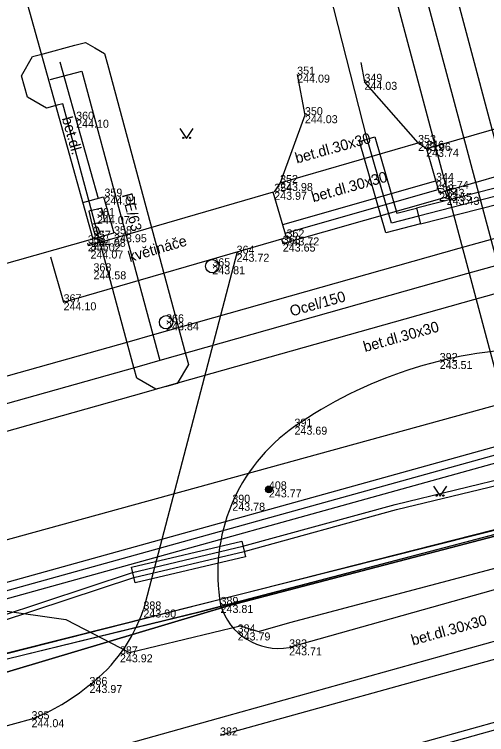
# Model space of a CAD drawing. Extents: x -599432 to -598680, y -1159407 to -1158632.
# Drawn here: x -599144.96 to -599127.27, y -1158925.7 to -1158898.71 of the extents above; entities that cross this region are included whole.
import ezdxf

# ---------------------------------------------------------------- set-up
doc = ezdxf.new("R2010")
doc.units = 0
for name, color, linetype in [('0004 VY - Body podrobné', 7, 'Continuous'), ('0005 VY - Body podrobné - čísla', 7, 'Continuous'), ('0006 VY - Body podrobné - výšky', 7, 'Continuous'), ('0007 ZA - Budova - zděná', 7, 'Continuous'), ('0014 ZA - Schody v terénu', 7, 'Continuous'), ('0025 ZA - Opěrná zeď', 7, 'Continuous'), ('0026 ZA - Polohopis - buňky', 7, 'Continuous'), ('0027 ZA - Silnice_cesta zpevněná', 7, 'Continuous'), ('0028 ZA - Silnice - nájezd na chodník', 7, 'Continuous'), ('0030 ZA - Chodník', 7, 'Continuous'), ('0031 ZA - Ostatní rozhraní', 7, 'Continuous'), ('0032 TE - Popis povrchu', 7, 'Continuous'), ('0034 ZA - Kultury - značky', 7, 'Continuous'), ('0074 TE - Vysvětlivky', 7, 'Continuous'), ('0075 ZA - BVK - kanalizace - buňky', 7, 'Continuous'), ('0116 PV - budova převzatá z mapy', 7, 'Continuous'), ('0202 PV - MUNI', 7, 'Continuous'), ('0206 PV - BVK - kanalizace - jednotná', 7, 'Continuous'), ('0211 PV - BVK - kanalizace - jednotná okraj', 7, 'Continuous'), ('0254 PV - TB - horkovod - vedení', 7, 'Continuous'), ('0255 PV - TB - horkovod - okraj', 7, 'Continuous'), ('0264 PV - TB - parovod mimo provoz', 7, 'Continuous'), ('0301 PV - RWE - popis', 7, 'Continuous'), ('0302 PV - RWE - NTL', 7, 'Continuous'), ('0303 PV - RWE - NTL přípojka', 7, 'Continuous'), ('0308 PV - RWE - ochranné pásmo', 7, 'Continuous'), ('0354 PV - EON - VN', 7, 'Continuous'), ('0359 PV - EON - sdělovací kabely', 7, 'Continuous'), ('0367 PV - EON - VN chránička', 7, 'Continuous'), ('0407 PV - TSB - kabelové vedení přibližný zákres', 7, 'Continuous'), ('0454 PV - O2 - kabel zaměřený', 7, 'Continuous'), ('0530 PV - T-mobile - optické kabely', 7, 'Continuous'), ('0552 PV - NETBOX - vedení', 7, 'Continuous'), ('0553 PV - NETBOX - chranička', 7, 'Continuous'), ('0652 PV - BKOM - kabely bez rozlišení', 7, 'Continuous'), ('0703 PV - DIAL TELECOM optický kabel', 7, 'Continuous'), ('0704 PV - ČD - kabely', 7, 'Continuous'), ('0750 ZA - nerozlišené sítě - buňky', 7, 'Continuous')]:
    doc.layers.add(name, color=color, linetype=linetype)

msp = doc.modelspace()

# ---------------------------------------------------------------- linework, layer by layer
at = {"layer": '0004 VY - Body podrobné'}
for p, q in [((-599134.37, -1158900.97), (-599134.37, -1158900.97)), ((-599131.85, -1158901.24), (-599131.85, -1158901.24)), ((-599134.08, -1158902.49), (-599134.08, -1158902.49)), ((-599142.65, -1158902.66), (-599142.65, -1158902.66)), ((-599129.84, -1158903.53), (-599129.84, -1158903.53)), ((-599129.54, -1158903.75), (-599129.54, -1158903.75)), ((-599129.17, -1158904.95), (-599129.17, -1158904.95)), ((-599135.01, -1158905.03), (-599135.01, -1158905.03)), ((-599135.23, -1158905.36), (-599135.23, -1158905.36)), ((-599129.05, -1158905.4), (-599129.05, -1158905.4)), ((-599141.59, -1158905.54), (-599141.59, -1158905.54)), ((-599128.77, -1158905.55), (-599128.77, -1158905.55)), ((-599141.87, -1158906.27), (-599141.87, -1158906.27)), ((-599142.02, -1158907.12), (-599142.02, -1158907.12)), ((-599141.23, -1158906.95), (-599141.23, -1158906.95)), ((-599134.77, -1158907.07), (-599134.77, -1158907.07)), ((-599142.21, -1158907.29), (-599142.21, -1158907.29)), ((-599134.91, -1158907.3), (-599134.91, -1158907.3)), ((-599142.11, -1158907.56), (-599142.11, -1158907.56)), ((-599136.64, -1158907.68), (-599136.64, -1158907.68)), ((-599137.55, -1158908.15), (-599137.55, -1158908.15)), ((-599142, -1158908.34), (-599142, -1158908.34)), ((-599143.12, -1158909.5), (-599143.12, -1158909.5)), ((-599139.28, -1158910.25), (-599139.28, -1158910.25)), ((-599129.03, -1158911.7), (-599129.03, -1158911.7)), ((-599134.47, -1158914.16), (-599134.47, -1158914.16)), ((-599135.43, -1158916.51), (-599135.43, -1158916.51)), ((-599136.8, -1158917.01), (-599136.8, -1158917.01)), ((-599137.24, -1158920.84), (-599137.24, -1158920.84)), ((-599140.13, -1158921.01), (-599140.13, -1158921.01)), ((-599136.6, -1158921.87), (-599136.6, -1158921.87)), ((-599134.67, -1158922.43), (-599134.67, -1158922.43)), ((-599141.01, -1158922.69), (-599141.01, -1158922.69)), ((-599142.15, -1158923.84), (-599142.15, -1158923.84)), ((-599144.32, -1158925.12), (-599144.32, -1158925.12))]:
    msp.add_line(p, q, dxfattribs=at)
at = {"layer": '0007 ZA - Budova - zděná'}
msp.add_line((-599202.3, -1158924.18), (-599142.02, -1158907.12), dxfattribs=at)
at = {"layer": '0014 ZA - Schody v terénu'}
for p, q in [((-599135.01, -1158905.03), (-599129.84, -1158903.53)), ((-599134.911, -1158906.586), (-599129.179, -1158904.953)), ((-599134.818, -1158906.906), (-599129.087, -1158905.272)), ((-599128.831, -1158905.337), (-599128.77, -1158905.55)), ((-599134.91, -1158907.3), (-599128.77, -1158905.55)), ((-599134.961, -1158907.126), (-599134.91, -1158907.3))]:
    msp.add_line(p, q, dxfattribs=at)
at = {"layer": '0025 ZA - Opěrná zeď'}
for p, q in [((-599122.539, -1158901.732), (-599129.527, -1158903.746)), ((-599129.05, -1158905.4), (-599120.55, -1158902.95)), ((-599129.527, -1158903.746), (-599129.05, -1158905.4)), ((-599135.265, -1158905.37), (-599142.183, -1158907.383)), ((-599134.77, -1158907.07), (-599135.265, -1158905.37)), ((-599143.12, -1158909.5), (-599134.77, -1158907.07)), ((-599142.183, -1158907.383), (-599142.21, -1158907.29)), ((-599143.615, -1158907.8), (-599143.12, -1158909.5))]:
    msp.add_line(p, q, dxfattribs=at)
at = {"layer": '0026 ZA - Polohopis - buňky'}
for radius in [0.125, 0.1, 0.075, 0.05, 0.025]:
    msp.add_circle((-599135.43, -1158916.51), radius, dxfattribs=at)
at = {"layer": '0027 ZA - Silnice_cesta zpevněná'}
msp.add_line((-599088.55, -1158912.2), (-599137.26, -1158925.73), dxfattribs=at)
at = {"layer": '0028 ZA - Silnice - nájezd na chodník'}
msp.add_line((-599088.5, -1158914.55), (-599147.65, -1158930.98), dxfattribs=at)
at = {"layer": '0030 ZA - Chodník'}
for p, q in [((-599131.988, -1158900.516), (-599131.85, -1158901.24)), ((-599134.37, -1158900.97), (-599134.08, -1158902.49)), ((-599129.84, -1158903.53), (-599131.85, -1158901.24)), ((-599134.08, -1158902.49), (-599135.01, -1158905.03)), ((-599129.527, -1158903.746), (-599129.84, -1158903.53)), ((-599135.01, -1158905.03), (-599135.23, -1158905.36)), ((-599136.621, -1158907.609), (-599140.13, -1158921.01)), ((-599120.617, -1158918.484), (-599134.67, -1158922.43)), ((-599144.32, -1158925.12), (-599169.23, -1158932.02))]:
    msp.add_line(p, q, dxfattribs=at)
for centre, radius, start, end in [((-599125.107, -1158927.621), 16.397, 91.584, 124.8223), ((-599130.655, -1158919.656), 6.69, 124.7637, 190.1916), ((-599135.071, -1158920.206), 2.26, 196.2914, 280.2204), ((-599145.738, -1158919.143), 5.911, 307.3777, 341.5853), ((-599147.291, -1158917.603), 8.082, 291.5684, 309.5011)]:
    msp.add_arc(centre, radius, start, end, dxfattribs=at)
at = {"layer": '0031 ZA - Ostatní rozhraní'}
for p, q in [((-599143.255, -1158900.493), (-599141.827, -1158905.606)), ((-599142.398, -1158905.766), (-599141.621, -1158905.549)), ((-599141.621, -1158905.549), (-599141.243, -1158906.903)), ((-599142.02, -1158907.12), (-599141.243, -1158906.903)), ((-599088.425, -1158914.82), (-599146.72, -1158931.012))]:
    msp.add_line(p, q, dxfattribs=at)
at = {"layer": '0034 ZA - Kultury - značky'}
for points in [[(-599138.762, -1158902.988), (-599138.512, -1158903.363), (-599138.262, -1158902.988)], [(-599129.268, -1158916.394), (-599129.018, -1158916.769), (-599128.768, -1158916.394)]]:
    msp.add_lwpolyline(points, dxfattribs=at)
for centre in [(-599138.637, -1158903.338), (-599138.387, -1158903.338), (-599129.143, -1158916.744), (-599128.893, -1158916.744)]:
    msp.add_circle(centre, 0.025, dxfattribs=at)
at = {"layer": '0075 ZA - BVK - kanalizace - buňky'}
for centre in [(-599137.55, -1158908.15), (-599139.28, -1158910.25)]:
    msp.add_circle(centre, 0.25, dxfattribs=at)
at = {"layer": '0116 PV - budova převzatá z mapy'}
msp.add_line((-599145.8, -1158893.59), (-599142.02, -1158907.12), dxfattribs=at)
at = {"layer": '0202 PV - MUNI'}
msp.add_lwpolyline([(-599146.637, -1158922.988), (-599125.848, -1158917.745), (-599099.176, -1158910.829), (-599079.1, -1158904.889), (-599063.715, -1158899.846), (-599061.634, -1158898.405), (-599061.066, -1158896.468), (-599061.778, -1158890.969), (-599061.202, -1158889.928), (-599056.191, -1158887.591), (-599053.917, -1158887.479), (-599048.522, -1158885.349), (-599047.385, -1158884.453), (-599040.021, -1158881.203), (-599032.673, -1158878.601), (-599020.545, -1158875.063), (-599018.496, -1158874.767), (-599015.655, -1158876.808), (-599014.942, -1158877.801)], dxfattribs=at)
at = {"layer": '0206 PV - BVK - kanalizace - jednotná'}
msp.add_line((-599158.607, -1158924.017), (-599091.321, -1158905.303), dxfattribs=at)
at = {"layer": '0211 PV - BVK - kanalizace - jednotná okraj'}
for p, q in [((-599158.687, -1158923.728), (-599091.402, -1158905.014)), ((-599091.241, -1158905.592), (-599158.526, -1158924.307))]:
    msp.add_line(p, q, dxfattribs=at)
at = {"layer": '0254 PV - TB - horkovod - vedení'}
msp.add_line((-599130.737, -1158893.547), (-599118.2, -1158940.655), dxfattribs=at)
at = {"layer": '0255 PV - TB - horkovod - okraj'}
for p, q in [((-599129.678, -1158893.249), (-599117.137, -1158940.372)), ((-599119.456, -1158940.213), (-599131.796, -1158893.845))]:
    msp.add_line(p, q, dxfattribs=at)
at = {"layer": '0264 PV - TB - parovod mimo provoz'}
msp.add_line((-599074.078, -1158898.846), (-599160.39, -1158922.56), dxfattribs=at)
at = {"layer": '0302 PV - RWE - NTL'}
msp.add_lwpolyline([(-599042.76, -1158885.49), (-599068.42, -1158892.17), (-599094.54, -1158899.36), (-599103.01, -1158901.75), (-599109.28, -1158903.4), (-599121.29, -1158906.57), (-599128.03, -1158908.44), (-599139.52, -1158911.687), (-599140.38, -1158911.93), (-599166.16, -1158919.18), (-599194.33, -1158927.1), (-599199.24, -1158928.46), (-599225.65, -1158935.9)], dxfattribs=at)
at = {"layer": '0303 PV - RWE - NTL přípojka'}
msp.add_lwpolyline([(-599143.618, -1158901.153), (-599142.443, -1158900.835), (-599139.52, -1158911.687)], dxfattribs=at)
at = {"layer": '0308 PV - RWE - ochranné pásmo'}
for points in [[(-599166.431, -1158918.217), (-599140.651, -1158910.968), (-599139.792, -1158910.725), (-599128.3, -1158907.477), (-599121.551, -1158905.605), (-599109.535, -1158902.433), (-599103.273, -1158900.785), (-599094.808, -1158898.397), (-599068.679, -1158891.204), (-599043.012, -1158884.522)], [(-599042.508, -1158886.458), (-599068.161, -1158893.136), (-599094.272, -1158900.323), (-599102.747, -1158902.715), (-599109.025, -1158904.367), (-599121.029, -1158907.535), (-599127.76, -1158909.403), (-599139.248, -1158912.649), (-599140.109, -1158912.892), (-599165.889, -1158920.143)]]:
    msp.add_lwpolyline(points, dxfattribs=at)
msp.add_lwpolyline([(-599144.279, -1158900.296), (-599143.879, -1158900.188), (-599142.704, -1158899.87), (-599142.304, -1158899.761), (-599141.945, -1158899.968), (-599141.585, -1158900.175), (-599141.477, -1158900.575), (-599138.554, -1158911.427), (-599138.446, -1158911.827), (-599138.86, -1158912.545), (-599139.26, -1158912.653), (-599139.66, -1158912.761), (-599140.378, -1158912.347), (-599140.486, -1158911.947), (-599143.148, -1158902.062), (-599143.357, -1158902.118), (-599143.757, -1158902.227), (-599144.475, -1158901.814), (-599144.583, -1158901.414), (-599144.692, -1158901.014)], close=True, dxfattribs=at)
at = {"layer": '0354 PV - EON - VN'}
for points in [[(-599145.539, -1158921.274), (-599140.537, -1158919.624), (-599136.405, -1158918.643), (-599130.705, -1158917.073), (-599126.184, -1158915.983), (-599122.341, -1158915.002), (-599120.4, -1158914.682), (-599115.645, -1158913.543), (-599111.287, -1158912.334), (-599109.596, -1158911.863), (-599106.311, -1158911.019), (-599105.916, -1158909.495), (-599106.798, -1158905.411), (-599107.107, -1158903.934), (-599107.313, -1158903.214), (-599107.021, -1158901.757), (-599106.185, -1158901.015), (-599105.203, -1158900.565)], [(-599145.481, -1158921.466), (-599140.483, -1158919.816), (-599136.355, -1158918.837), (-599130.655, -1158917.267), (-599126.136, -1158916.177), (-599122.299, -1158915.198), (-599120.36, -1158914.878), (-599115.595, -1158913.737), (-599111.233, -1158912.526), (-599109.544, -1158912.057), (-599106.208, -1158911.199), (-599105.476, -1158911.584), (-599104.034, -1158916.175), (-599102.994, -1158918.604), (-599101.447, -1158923.974), (-599100.22, -1158930.092), (-599099.87, -1158938.117), (-599099.769, -1158939.21), (-599099.658, -1158940.222)]]:
    msp.add_lwpolyline(points, dxfattribs=at)
at = {"layer": '0359 PV - EON - sdělovací kabely'}
msp.add_lwpolyline([(-599153, -1158925.67), (-599136.91, -1158920.86), (-599119.51, -1158916.31), (-599104.33, -1158911.91), (-599088.3, -1158908.08), (-599074.72, -1158903.34), (-599063.86, -1158900.66), (-599061.95, -1158898.88), (-599061.24, -1158895.32), (-599061.55, -1158893.87), (-599062.09, -1158890.79), (-599061.3, -1158889.79), (-599054.31, -1158887.73), (-599051.84, -1158888.39), (-598992.76, -1158891.74), (-598991.64, -1158891.24), (-598990.73, -1158890.27)], dxfattribs=at)
msp.add_lwpolyline([(-599153, -1158925.67), (-599136.91, -1158920.86), (-599119.51, -1158916.31), (-599104.33, -1158911.91), (-599088.3, -1158908.08), (-599074.72, -1158903.34), (-599063.86, -1158900.66), (-599061.95, -1158898.88), (-599061.24, -1158895.32), (-599061.55, -1158893.87), (-599062.09, -1158890.79), (-599061.3, -1158889.79), (-599054.31, -1158887.73), (-599051.84, -1158888.39), (-598992.76, -1158891.74), (-598991.64, -1158891.24), (-598990.73, -1158890.27)], dxfattribs=at)
at = {"layer": '0367 PV - EON - VN chránička'}
for p, q in [((-599140.579, -1158919.428), (-599136.449, -1158918.448)), ((-599136.449, -1158918.448), (-599136.311, -1158919.032)), ((-599136.311, -1158919.032), (-599140.441, -1158920.012)), ((-599140.441, -1158920.012), (-599140.579, -1158919.428))]:
    msp.add_line(p, q, dxfattribs=at)
at = {"layer": '0407 PV - TSB - kabelové vedení přibližný zákres'}
for p, q in [((-599134.644, -1158921.504), (-599126.606, -1158919.373)), ((-599146.829, -1158920.84), (-599143.039, -1158921.389)), ((-599143.039, -1158921.389), (-599140.654, -1158922.626)), ((-599140.654, -1158922.626), (-599136.507, -1158921.618)), ((-599136.507, -1158921.618), (-599135.818, -1158921.835)), ((-599135.818, -1158921.835), (-599134.644, -1158921.504))]:
    msp.add_line(p, q, dxfattribs=at)
at = {"layer": '0454 PV - O2 - kabel zaměřený'}
msp.add_lwpolyline([(-599146.63, -1158923.2), (-599137.96, -1158921.08), (-599126, -1158917.94), (-599115.1, -1158915.26), (-599086.38, -1158907.25), (-599065.99, -1158901.17), (-599063.3, -1158900.18)], dxfattribs=at)
at = {"layer": '0530 PV - T-mobile - optické kabely'}
for points in [[(-599136.91, -1158920.859), (-599119.509, -1158916.309)], [(-599137.957, -1158921.076), (-599125.997, -1158917.936)], [(-599153, -1158925.67), (-599136.91, -1158920.859)], [(-599146.626, -1158923.197), (-599137.957, -1158921.076)]]:
    msp.add_lwpolyline(points, dxfattribs=at)
at = {"layer": '0552 PV - NETBOX - vedení'}
msp.add_lwpolyline([(-599102.74, -1158899.21), (-599108.37, -1158900.95), (-599108.37, -1158900.95), (-599111.05, -1158901.6), (-599111.05, -1158901.6), (-599120.1, -1158903.98), (-599120.1, -1158903.98), (-599126.14, -1158905.33), (-599126.14, -1158905.33), (-599129.83, -1158906.27), (-599130.84, -1158906.53), (-599131.75, -1158903.39), (-599131.75, -1158903.39), (-599133.77, -1158895.45)], dxfattribs=at)
at = {"layer": '0553 PV - NETBOX - chranička'}
for points in [[(-599129.756, -1158906.561), (-599131.047, -1158906.893), (-599132.038, -1158903.474), (-599131.462, -1158903.306), (-599130.633, -1158906.167), (-599129.904, -1158905.979), (-599129.756, -1158906.561)], [(-599126.214, -1158905.039), (-599129.904, -1158905.979), (-599129.756, -1158906.561), (-599126.066, -1158905.621), (-599126.214, -1158905.039)]]:
    msp.add_lwpolyline(points, dxfattribs=at)
at = {"layer": '0652 PV - BKOM - kabely bez rozlišení'}
msp.add_lwpolyline([(-599152.64, -1158929.37), (-599137, -1158924.99), (-599119.82, -1158920.2), (-599103.66, -1158915.75), (-599086.95, -1158911.13), (-599069.54, -1158906.27), (-599056.01, -1158902.46)], dxfattribs=at)
at = {"layer": '0703 PV - DIAL TELECOM optický kabel'}
msp.add_lwpolyline([(-599061.55, -1158893.87), (-599061.24, -1158895.32), (-599061.95, -1158898.88), (-599063.86, -1158900.66), (-599074.72, -1158903.34), (-599088.3, -1158908.08), (-599104.33, -1158911.91), (-599119.51, -1158916.31), (-599136.91, -1158920.86), (-599153, -1158925.67), (-599169.02, -1158930.6), (-599175.84, -1158932.87), (-599181.15, -1158933.71), (-599192.69, -1158937.18), (-599194.75, -1158937.1), (-599197.14, -1158935.93), (-599198.47, -1158933.96), (-599200.36, -1158929.03), (-599200.83, -1158928.66), (-599207.11, -1158930.84)], dxfattribs=at)
at = {"layer": '0704 PV - ČD - kabely'}
msp.add_lwpolyline([(-599063.507, -1158900.144), (-599114.022, -1158914.733), (-599146.63, -1158923.02)], dxfattribs=at)
at = {"layer": '0750 ZA - nerozlišené sítě - buňky'}
for p, q in [((-599141.683, -1158905.97), (-599142.17, -1158906.083)), ((-599141.57, -1158906.457), (-599141.683, -1158905.97)), ((-599142.17, -1158906.083), (-599142.057, -1158906.57)), ((-599142.057, -1158906.57), (-599141.57, -1158906.457))]:
    msp.add_line(p, q, dxfattribs=at)

# ---------------------------------------------------------------- texts
at = {"layer": '0005 VY - Body podrobné - čísla'}
for s, p in [('351', (-599134.37, -1158900.97)), ('349', (-599131.85, -1158901.24)), ('350', (-599134.08, -1158902.49)), ('360', (-599142.65, -1158902.66)), ('353', (-599129.84, -1158903.53)), ('346', (-599129.54, -1158903.75)), ('352', (-599135.01, -1158905.03)), ('344', (-599129.17, -1158904.95)), ('359', (-599141.59, -1158905.54)), ('354', (-599135.23, -1158905.36)), ('345', (-599129.05, -1158905.4)), ('343', (-599128.77, -1158905.55)), ('361', (-599141.87, -1158906.27)), ('357', (-599142.02, -1158907.12)), ('358', (-599141.23, -1158906.95)), ('362', (-599134.77, -1158907.07)), ('356', (-599142.21, -1158907.29)), ('363', (-599134.91, -1158907.3)), ('355', (-599142.11, -1158907.56)), ('364', (-599136.64, -1158907.68)), ('365', (-599137.55, -1158908.15)), ('368', (-599142, -1158908.34)), ('367', (-599143.12, -1158909.5)), ('366', (-599139.28, -1158910.25)), ('392', (-599129.03, -1158911.7)), ('391', (-599134.47, -1158914.16)), ('408', (-599135.43, -1158916.51)), ('390', (-599136.8, -1158917.01)), ('389', (-599137.24, -1158920.84)), ('388', (-599140.13, -1158921.01)), ('384', (-599136.6, -1158921.87)), ('383', (-599134.67, -1158922.43)), ('387', (-599141.01, -1158922.69)), ('386', (-599142.15, -1158923.84)), ('385', (-599144.32, -1158925.12)), ('382', (-599137.26, -1158925.73))]:
    msp.add_text(s, height=0.3, dxfattribs=at).set_placement(p)
at = {"layer": '0006 VY - Body podrobné - výšky'}
for s, p in [('244.09', (-599134.37, -1158901.27)), ('244.03', (-599131.85, -1158901.54)), ('244.03', (-599134.08, -1158902.79)), ('244.10', (-599142.65, -1158902.96)), ('243.96', (-599129.84, -1158903.83)), ('243.74', (-599129.54, -1158904.05)), ('243.74', (-599129.17, -1158905.25)), ('243.98', (-599135.01, -1158905.33)), ('244.01', (-599141.59, -1158905.84)), ('243.97', (-599135.23, -1158905.66)), ('243.55', (-599129.05, -1158905.7)), ('243.43', (-599128.77, -1158905.85)), ('244.07', (-599141.87, -1158906.57)), ('244.08', (-599142.02, -1158907.42)), ('243.95', (-599141.23, -1158907.25)), ('243.72', (-599134.77, -1158907.37)), ('244.02', (-599142.21, -1158907.59)), ('243.65', (-599134.91, -1158907.6)), ('244.07', (-599142.11, -1158907.86)), ('243.72', (-599136.64, -1158907.98)), ('243.81', (-599137.55, -1158908.45)), ('244.58', (-599142, -1158908.64)), ('244.10', (-599143.12, -1158909.8)), ('243.84', (-599139.28, -1158910.55)), ('243.51', (-599129.03, -1158912)), ('243.69', (-599134.47, -1158914.46)), ('243.77', (-599135.43, -1158916.81)), ('243.78', (-599136.8, -1158917.31)), ('243.81', (-599137.24, -1158921.14)), ('243.90', (-599140.13, -1158921.31)), ('243.79', (-599136.6, -1158922.17)), ('243.71', (-599134.67, -1158922.73)), ('243.92', (-599141.01, -1158922.99)), ('243.97', (-599142.15, -1158924.14)), ('244.04', (-599144.32, -1158925.42))]:
    msp.add_text(s, height=0.3, dxfattribs=at).set_placement(p)
at = {"layer": '0032 TE - Popis povrchu'}
for s, rotation, p in [('bet.dl.', 285.6093, (-599143.187, -1158902.605)), ('bet.dl.30x30', 15.5705, (-599134.384, -1158904.303)), ('bet.dl.30x30', 15.5705, (-599133.77, -1158905.756)), ('b.', 15.6093, (-599141.998, -1158907.004)), ('bet.dl.30x30', 15.5705, (-599131.83, -1158911.368)), ('bet.dl.30x30', 15.5705, (-599130.038, -1158922.362))]:
    msp.add_text(s, height=0.4, rotation=rotation, dxfattribs=at).set_placement(p)
at = {"layer": '0074 TE - Vysvětlivky'}
msp.add_text('květináče', height=0.4, rotation=16.2259, dxfattribs=at).set_placement((-599140.637, -1158907.996))
at = {"layer": '0301 PV - RWE - popis'}
for s, rotation, p in [('PE/63', 285.0749, (-599140.94, -1158905.473)), ('Ocel/150', 15.78, (-599134.582, -1158910.035))]:
    msp.add_text(s, height=0.4, rotation=rotation, dxfattribs=at).set_placement(p)

doc.saveas('drawing.dxf')
